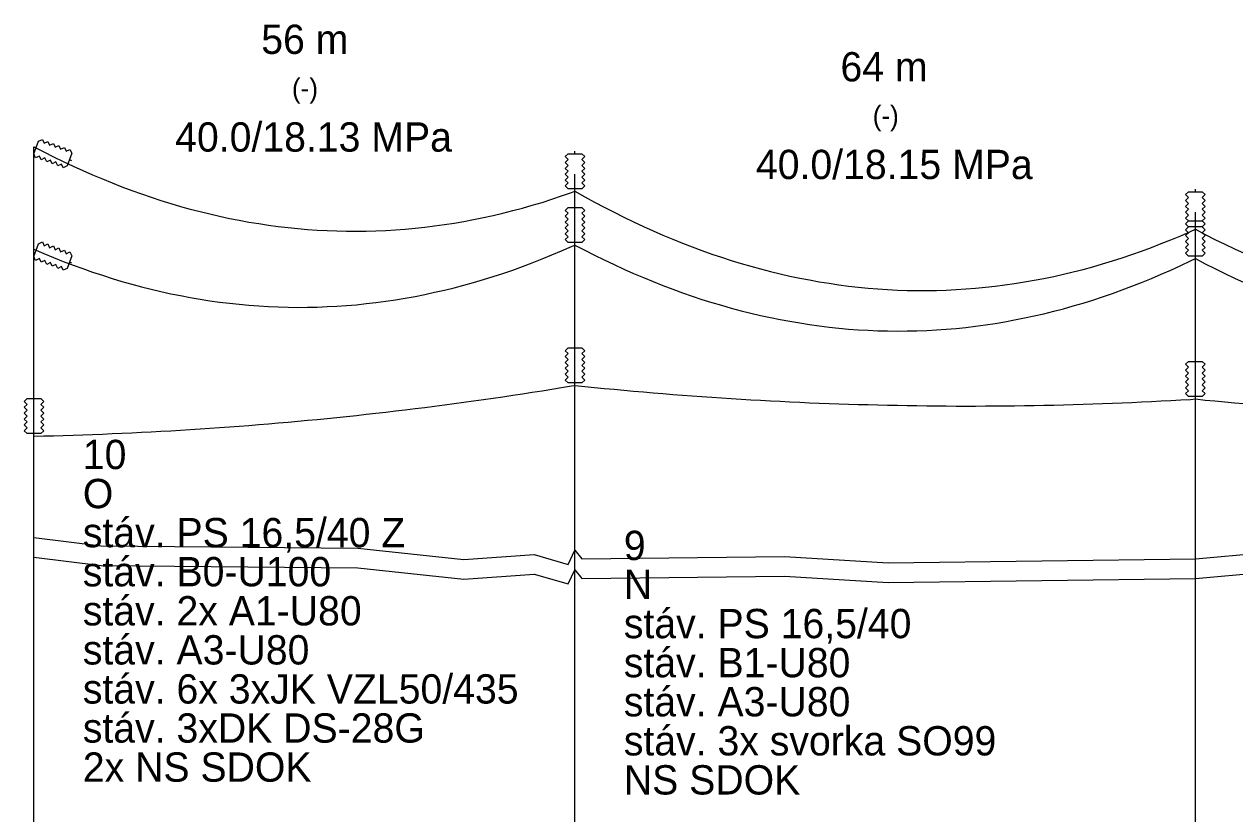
# Model space of a CAD drawing. Extents: x -21 to 628, y 809 to 990.
# Drawn here: x -1 to 122.9, y 900 to 980.8 of the extents above; entities that cross this region are included whole.
import ezdxf

# ---------------------------------------------------------------- set-up
doc = ezdxf.new("R2010")
doc.units = 0
for name, color, linetype in [('Vrstva 11', 7, 'Continuous'), ('Vrstva 12', 7, 'Continuous'), ('Vrstva 13', 7, 'Continuous'), ('Vrstva 14', 7, 'Continuous'), ('Vrstva 15', 7, 'Continuous'), ('Vrstva 29', 7, 'Continuous'), ('Vrstva 3', 7, 'Continuous')]:
    doc.layers.add(name, color=color, linetype=linetype)

msp = doc.modelspace()

# ---------------------------------------------------------------- linework, layer by layer
at = {"layer": 'Vrstva 11'}
for points in [[(0, 968.25), (1, 967.73), (2, 967.23), (3, 966.74), (4, 966.27), (5, 965.82), (6, 965.38), (7, 964.95), (8, 964.55), (9, 964.16), (10, 963.78), (11, 963.42), (12, 963.08), (13, 962.76), (14, 962.45), (15, 962.15), (16, 961.87), (17, 961.61), (18, 961.37), (19, 961.14), (20, 960.92), (21, 960.72), (22, 960.54), (23, 960.38), (24, 960.23), (25, 960.09), (26, 959.98), (27, 959.88), (28, 959.79), (29, 959.72), (30, 959.67), (31, 959.63), (32, 959.61), (33, 959.6), (34, 959.62), (35, 959.64), (36, 959.69), (37, 959.75), (38, 959.82), (39, 959.91), (40, 960.02), (41, 960.14), (42, 960.28), (43, 960.44), (44, 960.61), (45, 960.8), (46, 961), (47, 961.22), (48, 961.46), (49, 961.71), (50, 961.98), (51, 962.26), (52, 962.56), (53, 962.88), (54, 963.21), (55, 963.56), (55.37, 963.69)], [(55.37, 963.69), (56.37, 963.13), (57.37, 962.58), (58.37, 962.05), (59.37, 961.54), (60.37, 961.04), (61.37, 960.55), (62.37, 960.09), (63.37, 959.64), (64.37, 959.2), (65.37, 958.78), (66.37, 958.38), (67.37, 957.99), (68.37, 957.62), (69.37, 957.27), (70.37, 956.93), (71.37, 956.61), (72.37, 956.3), (73.37, 956.01), (74.37, 955.74), (75.37, 955.48), (76.37, 955.24), (77.37, 955.01), (78.37, 954.8), (79.37, 954.61), (80.37, 954.43), (81.37, 954.27), (82.37, 954.12), (83.37, 953.99), (84.37, 953.88), (85.37, 953.78), (86.37, 953.7), (87.37, 953.63), (88.37, 953.58), (89.37, 953.55), (90.37, 953.53), (91.37, 953.53), (92.37, 953.55), (93.37, 953.58), (94.37, 953.63), (95.37, 953.69), (96.37, 953.77), (97.37, 953.86), (98.37, 953.98), (99.37, 954.1), (100.37, 954.25), (101.37, 954.41), (102.37, 954.58), (103.37, 954.77), (104.37, 954.98), (105.37, 955.21), (106.37, 955.45), (107.37, 955.7), (108.37, 955.97), (109.37, 956.26), (110.37, 956.57), (111.37, 956.89), (112.37, 957.22), (113.37, 957.57), (114.37, 957.94), (115.37, 958.33), (116.37, 958.73), (117.37, 959.14), (118.37, 959.58), (118.87, 959.8)], [(118.87, 959.8), (119.87, 959.28), (120.87, 958.77), (121.87, 958.28), (122.87, 957.81), (123.87, 957.35)], [(0, 957.75), (1, 957.32), (2, 956.91), (3, 956.51), (4, 956.13), (5, 955.77), (6, 955.42), (7, 955.09), (8, 954.77), (9, 954.47), (10, 954.19), (11, 953.92), (12, 953.67), (13, 953.43), (14, 953.21), (15, 953.01), (16, 952.82), (17, 952.65), (18, 952.49), (19, 952.35), (20, 952.23), (21, 952.12), (22, 952.03), (23, 951.95), (24, 951.89), (25, 951.85), (26, 951.82), (27, 951.81), (28, 951.82), (29, 951.84), (30, 951.88), (31, 951.93), (32, 952), (33, 952.08), (34, 952.19), (35, 952.3), (36, 952.44), (37, 952.59), (38, 952.75), (39, 952.93), (40, 953.13), (41, 953.35), (42, 953.58), (43, 953.82), (44, 954.08), (45, 954.36), (46, 954.66), (47, 954.97), (48, 955.29), (49, 955.63), (50, 955.99), (51, 956.37), (52, 956.76), (53, 957.17), (54, 957.59), (55, 958.03), (55.37, 958.19)], [(0, 957.75), (1, 957.32), (2, 956.91), (3, 956.51), (4, 956.13), (5, 955.77), (6, 955.42), (7, 955.09), (8, 954.77), (9, 954.47), (10, 954.19), (11, 953.92), (12, 953.67), (13, 953.43), (14, 953.21), (15, 953.01), (16, 952.82), (17, 952.65), (18, 952.49), (19, 952.35), (20, 952.23), (21, 952.12), (22, 952.03), (23, 951.95), (24, 951.89), (25, 951.85), (26, 951.82), (27, 951.81), (28, 951.82), (29, 951.84), (30, 951.88), (31, 951.93), (32, 952), (33, 952.08), (34, 952.19), (35, 952.3), (36, 952.44), (37, 952.59), (38, 952.75), (39, 952.93), (40, 953.13), (41, 953.35), (42, 953.58), (43, 953.82), (44, 954.08), (45, 954.36), (46, 954.66), (47, 954.97), (48, 955.29), (49, 955.63), (50, 955.99), (51, 956.37), (52, 956.76), (53, 957.17), (54, 957.59), (55, 958.03), (55.37, 958.19)], [(55.37, 958.19), (56.37, 957.67), (57.37, 957.16), (58.37, 956.67), (59.37, 956.19), (60.37, 955.73), (61.37, 955.29), (62.37, 954.86), (63.37, 954.45), (64.37, 954.05), (65.37, 953.68), (66.37, 953.31), (67.37, 952.97), (68.37, 952.63), (69.37, 952.32), (70.37, 952.02), (71.37, 951.74), (72.37, 951.47), (73.37, 951.22), (74.37, 950.98), (75.37, 950.77), (76.37, 950.56), (77.37, 950.38), (78.37, 950.21), (79.37, 950.05), (80.37, 949.91), (81.37, 949.79), (82.37, 949.68), (83.37, 949.59), (84.37, 949.52), (85.37, 949.46), (86.37, 949.42), (87.37, 949.39), (88.37, 949.38), (89.37, 949.39), (90.37, 949.41), (91.37, 949.45), (92.37, 949.51), (93.37, 949.58), (94.37, 949.66), (95.37, 949.76), (96.37, 949.88), (97.37, 950.02), (98.37, 950.17), (99.37, 950.34), (100.37, 950.52), (101.37, 950.72), (102.37, 950.93), (103.37, 951.16), (104.37, 951.41), (105.37, 951.67), (106.37, 951.95), (107.37, 952.25), (108.37, 952.56), (109.37, 952.89), (110.37, 953.23), (111.37, 953.59), (112.37, 953.97), (113.37, 954.36), (114.37, 954.77), (115.37, 955.19), (116.37, 955.63), (117.37, 956.09), (118.37, 956.56), (118.87, 956.8)], [(55.37, 958.19), (56.37, 957.67), (57.37, 957.16), (58.37, 956.67), (59.37, 956.19), (60.37, 955.73), (61.37, 955.29), (62.37, 954.86), (63.37, 954.45), (64.37, 954.05), (65.37, 953.68), (66.37, 953.31), (67.37, 952.97), (68.37, 952.63), (69.37, 952.32), (70.37, 952.02), (71.37, 951.74), (72.37, 951.47), (73.37, 951.22), (74.37, 950.98), (75.37, 950.77), (76.37, 950.56), (77.37, 950.38), (78.37, 950.21), (79.37, 950.05), (80.37, 949.91), (81.37, 949.79), (82.37, 949.68), (83.37, 949.59), (84.37, 949.52), (85.37, 949.46), (86.37, 949.42), (87.37, 949.39), (88.37, 949.38), (89.37, 949.39), (90.37, 949.41), (91.37, 949.45), (92.37, 949.51), (93.37, 949.58), (94.37, 949.66), (95.37, 949.76), (96.37, 949.88), (97.37, 950.02), (98.37, 950.17), (99.37, 950.34), (100.37, 950.52), (101.37, 950.72), (102.37, 950.93), (103.37, 951.16), (104.37, 951.41), (105.37, 951.67), (106.37, 951.95), (107.37, 952.25), (108.37, 952.56), (109.37, 952.89), (110.37, 953.23), (111.37, 953.59), (112.37, 953.97), (113.37, 954.36), (114.37, 954.77), (115.37, 955.19), (116.37, 955.63), (117.37, 956.09), (118.37, 956.56), (118.87, 956.8)], [(118.87, 956.8), (119.87, 956.28), (120.87, 955.77), (121.87, 955.28), (122.87, 954.81), (123.87, 954.35)], [(118.87, 956.8), (119.87, 956.28), (120.87, 955.77), (121.87, 955.28), (122.87, 954.81), (123.87, 954.35)], [(0, 938.62), (1, 938.65), (2, 938.67), (3, 938.7), (4, 938.73), (5, 938.76), (6, 938.8), (7, 938.84), (8, 938.88), (9, 938.92), (10, 938.97), (11, 939.02), (12, 939.07), (13, 939.12), (14, 939.18), (15, 939.24), (16, 939.3), (17, 939.37), (18, 939.43), (19, 939.5), (20, 939.58), (21, 939.65), (22, 939.73), (23, 939.81), (24, 939.89), (25, 939.98), (26, 940.06), (27, 940.16), (28, 940.25), (29, 940.34), (30, 940.44), (31, 940.54), (32, 940.65), (33, 940.75), (34, 940.86), (35, 940.97), (36, 941.09), (37, 941.21), (38, 941.33), (39, 941.45), (40, 941.57), (41, 941.7), (42, 941.83), (43, 941.96), (44, 942.1), (45, 942.23), (46, 942.38), (47, 942.52), (48, 942.66), (49, 942.81), (50, 942.96), (51, 943.12), (52, 943.27), (53, 943.43), (54, 943.59), (55, 943.76), (55.37, 943.82)], [(55.37, 943.82), (56.37, 943.71), (57.37, 943.61), (58.37, 943.51), (59.37, 943.42), (60.37, 943.33), (61.37, 943.23), (62.37, 943.15), (63.37, 943.06), (64.37, 942.98), (65.37, 942.9), (66.37, 942.82), (67.37, 942.75), (68.37, 942.67), (69.37, 942.6), (70.37, 942.54), (71.37, 942.47), (72.37, 942.41), (73.37, 942.35), (74.37, 942.3), (75.37, 942.24), (76.37, 942.19), (77.37, 942.14), (78.37, 942.1), (79.37, 942.05), (80.37, 942.01), (81.37, 941.97), (82.37, 941.94), (83.37, 941.9), (84.37, 941.87), (85.37, 941.85), (86.37, 941.82), (87.37, 941.8), (88.37, 941.78), (89.37, 941.76), (90.37, 941.75), (91.37, 941.73), (92.37, 941.73), (93.37, 941.72), (94.37, 941.71), (95.37, 941.71), (96.37, 941.71), (97.37, 941.72), (98.37, 941.72), (99.37, 941.73), (100.37, 941.74), (101.37, 941.76), (102.37, 941.77), (103.37, 941.79), (104.37, 941.81), (105.37, 941.84), (106.37, 941.87), (107.37, 941.9), (108.37, 941.93), (109.37, 941.96), (110.37, 942), (111.37, 942.04), (112.37, 942.08), (113.37, 942.13), (114.37, 942.18), (115.37, 942.23), (116.37, 942.28), (117.37, 942.34), (118.37, 942.39), (118.87, 942.43)], [(118.87, 942.43), (119.87, 942.32), (120.87, 942.23), (121.87, 942.13), (122.87, 942.04), (123.87, 941.95)]]:
    msp.add_lwpolyline(points, dxfattribs=at)
at = {"layer": 'Vrstva 14'}
for p, q in [((0, 898.25), (0, 968.25)), ((55.37, 896.94), (55.37, 965.44)), ((118.87, 896.05), (118.87, 961.55))]:
    msp.add_line(p, q, dxfattribs=at)
at = {"layer": 'Vrstva 29'}
for points in [[(0, 967.51), (0.47, 968.82), (0.86, 969), (1.04, 968.62), (1.42, 968.8), (1.6, 968.41), (1.99, 968.59), (2.17, 968.21), (2.55, 968.39), (2.73, 968), (3.11, 968.18), (3.29, 967.8), (3.68, 967.98), (3.86, 967.59), (3.38, 966.28), (2.99, 966.1), (2.81, 966.48), (2.43, 966.3), (2.25, 966.69), (1.87, 966.51), (1.69, 966.89), (1.3, 966.71), (1.12, 967.1), (0.74, 966.92), (0.56, 967.3), (0.17, 967.12)], [(56.07, 963.94), (54.67, 963.94), (54.37, 964.24), (54.67, 964.54), (54.37, 964.84), (54.67, 965.14), (54.37, 965.44), (54.67, 965.74), (54.37, 966.04), (54.67, 966.34), (54.37, 966.64), (54.67, 966.94), (54.37, 967.24), (54.67, 967.54), (56.07, 967.54), (56.37, 967.24), (56.07, 966.94), (56.37, 966.64), (56.07, 966.34), (56.37, 966.04), (56.07, 965.74), (56.37, 965.44), (56.07, 965.14), (56.37, 964.84), (56.07, 964.54), (56.37, 964.24)], [(56.07, 963.94), (54.67, 963.94), (54.37, 964.24), (54.67, 964.54), (54.37, 964.84), (54.67, 965.14), (54.37, 965.44), (54.67, 965.74), (54.37, 966.04), (54.67, 966.34), (54.37, 966.64), (54.67, 966.94), (54.37, 967.24), (54.67, 967.54), (56.07, 967.54), (56.37, 967.24), (56.07, 966.94), (56.37, 966.64), (56.07, 966.34), (56.37, 966.04), (56.07, 965.74), (56.37, 965.44), (56.07, 965.14), (56.37, 964.84), (56.07, 964.54), (56.37, 964.24)], [(119.57, 960.05), (118.17, 960.05), (117.87, 960.35), (118.17, 960.65), (117.87, 960.95), (118.17, 961.25), (117.87, 961.55), (118.17, 961.85), (117.87, 962.15), (118.17, 962.45), (117.87, 962.75), (118.17, 963.05), (117.87, 963.35), (118.17, 963.65), (119.57, 963.65), (119.87, 963.35), (119.57, 963.05), (119.87, 962.75), (119.57, 962.45), (119.87, 962.15), (119.57, 961.85), (119.87, 961.55), (119.57, 961.25), (119.87, 960.95), (119.57, 960.65), (119.87, 960.35)], [(56.07, 958.44), (54.67, 958.44), (54.37, 958.74), (54.67, 959.04), (54.37, 959.34), (54.67, 959.64), (54.37, 959.94), (54.67, 960.24), (54.37, 960.54), (54.67, 960.84), (54.37, 961.14), (54.67, 961.44), (54.37, 961.74), (54.67, 962.04), (56.07, 962.04), (56.37, 961.74), (56.07, 961.44), (56.37, 961.14), (56.07, 960.84), (56.37, 960.54), (56.07, 960.24), (56.37, 959.94), (56.07, 959.64), (56.37, 959.34), (56.07, 959.04), (56.37, 958.74)], [(56.07, 958.44), (54.67, 958.44), (54.37, 958.74), (54.67, 959.04), (54.37, 959.34), (54.67, 959.64), (54.37, 959.94), (54.67, 960.24), (54.37, 960.54), (54.67, 960.84), (54.37, 961.14), (54.67, 961.44), (54.37, 961.74), (54.67, 962.04), (56.07, 962.04), (56.37, 961.74), (56.07, 961.44), (56.37, 961.14), (56.07, 960.84), (56.37, 960.54), (56.07, 960.24), (56.37, 959.94), (56.07, 959.64), (56.37, 959.34), (56.07, 959.04), (56.37, 958.74)], [(56.07, 958.44), (54.67, 958.44), (54.37, 958.74), (54.67, 959.04), (54.37, 959.34), (54.67, 959.64), (54.37, 959.94), (54.67, 960.24), (54.37, 960.54), (54.67, 960.84), (54.37, 961.14), (54.67, 961.44), (54.37, 961.74), (54.67, 962.04), (56.07, 962.04), (56.37, 961.74), (56.07, 961.44), (56.37, 961.14), (56.07, 960.84), (56.37, 960.54), (56.07, 960.24), (56.37, 959.94), (56.07, 959.64), (56.37, 959.34), (56.07, 959.04), (56.37, 958.74)], [(56.07, 958.44), (54.67, 958.44), (54.37, 958.74), (54.67, 959.04), (54.37, 959.34), (54.67, 959.64), (54.37, 959.94), (54.67, 960.24), (54.37, 960.54), (54.67, 960.84), (54.37, 961.14), (54.67, 961.44), (54.37, 961.74), (54.67, 962.04), (56.07, 962.04), (56.37, 961.74), (56.07, 961.44), (56.37, 961.14), (56.07, 960.84), (56.37, 960.54), (56.07, 960.24), (56.37, 959.94), (56.07, 959.64), (56.37, 959.34), (56.07, 959.04), (56.37, 958.74)], [(119.57, 957.05), (118.17, 957.05), (117.87, 957.35), (118.17, 957.65), (117.87, 957.95), (118.17, 958.25), (117.87, 958.55), (118.17, 958.85), (117.87, 959.15), (118.17, 959.45), (117.87, 959.75), (118.17, 960.05), (117.87, 960.35), (118.17, 960.65), (119.57, 960.65), (119.87, 960.35), (119.57, 960.05), (119.87, 959.75), (119.57, 959.45), (119.87, 959.15), (119.57, 958.85), (119.87, 958.55), (119.57, 958.25), (119.87, 957.95), (119.57, 957.65), (119.87, 957.35)], [(119.57, 957.05), (118.17, 957.05), (117.87, 957.35), (118.17, 957.65), (117.87, 957.95), (118.17, 958.25), (117.87, 958.55), (118.17, 958.85), (117.87, 959.15), (118.17, 959.45), (117.87, 959.75), (118.17, 960.05), (117.87, 960.35), (118.17, 960.65), (119.57, 960.65), (119.87, 960.35), (119.57, 960.05), (119.87, 959.75), (119.57, 959.45), (119.87, 959.15), (119.57, 958.85), (119.87, 958.55), (119.57, 958.25), (119.87, 957.95), (119.57, 957.65), (119.87, 957.35)], [(0, 957.01), (0.47, 958.32), (0.86, 958.5), (1.04, 958.12), (1.42, 958.3), (1.6, 957.91), (1.99, 958.09), (2.17, 957.71), (2.55, 957.89), (2.73, 957.5), (3.11, 957.68), (3.29, 957.3), (3.68, 957.48), (3.86, 957.09), (3.38, 955.78), (2.99, 955.6), (2.81, 955.98), (2.43, 955.8), (2.25, 956.19), (1.87, 956.01), (1.69, 956.39), (1.3, 956.21), (1.12, 956.6), (0.74, 956.42), (0.56, 956.8), (0.17, 956.62)], [(0, 957.01), (0.47, 958.32), (0.86, 958.5), (1.04, 958.12), (1.42, 958.3), (1.6, 957.91), (1.99, 958.09), (2.17, 957.71), (2.55, 957.89), (2.73, 957.5), (3.11, 957.68), (3.29, 957.3), (3.68, 957.48), (3.86, 957.09), (3.38, 955.78), (2.99, 955.6), (2.81, 955.98), (2.43, 955.8), (2.25, 956.19), (1.87, 956.01), (1.69, 956.39), (1.3, 956.21), (1.12, 956.6), (0.74, 956.42), (0.56, 956.8), (0.17, 956.62)], [(56.07, 944.07), (54.67, 944.07), (54.37, 944.37), (54.67, 944.67), (54.37, 944.97), (54.67, 945.27), (54.37, 945.57), (54.67, 945.87), (54.37, 946.17), (54.67, 946.47), (54.37, 946.77), (54.67, 947.07), (54.37, 947.37), (54.67, 947.67), (56.07, 947.67), (56.37, 947.37), (56.07, 947.07), (56.37, 946.77), (56.07, 946.47), (56.37, 946.17), (56.07, 945.87), (56.37, 945.57), (56.07, 945.27), (56.37, 944.97), (56.07, 944.67), (56.37, 944.37)], [(119.57, 942.68), (118.17, 942.68), (117.87, 942.98), (118.17, 943.27), (117.87, 943.58), (118.17, 943.88), (117.87, 944.18), (118.17, 944.48), (117.87, 944.77), (118.17, 945.08), (117.87, 945.38), (118.17, 945.68), (117.87, 945.98), (118.17, 946.27), (119.57, 946.27), (119.87, 945.98), (119.57, 945.68), (119.87, 945.38), (119.57, 945.08), (119.87, 944.77), (119.57, 944.48), (119.87, 944.18), (119.57, 943.88), (119.87, 943.58), (119.57, 943.27), (119.87, 942.98)], [(0.7, 938.88), (-0.7, 938.88), (-1, 939.18), (-0.7, 939.48), (-1, 939.77), (-0.7, 940.08), (-1, 940.38), (-0.7, 940.68), (-1, 940.98), (-0.7, 941.27), (-1, 941.58), (-0.7, 941.88), (-1, 942.18), (-0.7, 942.48), (0.7, 942.48), (1, 942.18), (0.7, 941.88), (1, 941.58), (0.7, 941.27), (1, 940.98), (0.7, 940.68), (1, 940.38), (0.7, 940.08), (1, 939.77), (0.7, 939.48), (1, 939.18)]]:
    msp.add_lwpolyline(points, close=True, dxfattribs=at)
for points in [[(0, 968.25), (0.23, 968.16)], [(55.37, 967.54), (55.37, 967.79)], [(55.37, 967.54), (55.37, 967.79)], [(3.62, 966.93), (3.85, 966.85)], [(55.37, 963.69), (55.37, 963.94)], [(55.37, 963.69), (55.37, 963.94)], [(118.87, 963.65), (118.87, 963.9)], [(55.37, 962.04), (55.37, 962.29)], [(55.37, 962.04), (55.37, 962.29)], [(55.37, 962.04), (55.37, 962.29)], [(55.37, 962.04), (55.37, 962.29)], [(118.87, 960.65), (118.87, 960.9)], [(118.87, 960.65), (118.87, 960.9)], [(118.87, 959.8), (118.87, 960.05)], [(55.37, 958.19), (55.37, 958.44)], [(55.37, 958.19), (55.37, 958.44)], [(55.37, 958.19), (55.37, 958.44)], [(55.37, 958.19), (55.37, 958.44)], [(0, 957.75), (0.23, 957.66)], [(0, 957.75), (0.23, 957.66)], [(118.87, 956.8), (118.87, 957.05)], [(118.87, 956.8), (118.87, 957.05)], [(3.62, 956.43), (3.85, 956.35)], [(3.62, 956.43), (3.85, 956.35)], [(55.37, 947.67), (55.37, 947.92)], [(118.87, 946.27), (118.87, 946.52)], [(55.37, 943.82), (55.37, 944.07)], [(0, 942.48), (0, 942.73)], [(118.87, 942.43), (118.87, 942.68)], [(0, 938.62), (0, 938.88)]]:
    msp.add_lwpolyline(points, dxfattribs=at)
at = {"layer": 'Vrstva 3'}
for p, q in [((0, 928.25), (6.86, 927.4)), ((6.86, 927.4), (33.13, 927.15)), ((33.13, 927.15), (43.99, 926)), ((54.66, 925.5), (55.36, 926.95)), ((55.36, 926.95), (55.37, 926.94)), ((55.37, 926.94), (56.06, 926.05)), ((118.87, 926.05), (136.97, 927.7)), ((0, 926.25), (6.86, 925.4)), ((0, 926.25), (6.86, 925.4)), ((0, 926.25), (6.86, 925.4)), ((43.99, 926), (51.19, 926.5)), ((51.19, 926.5), (54.66, 925.5)), ((56.06, 926.05), (76.8, 926.3)), ((76.8, 926.3), (87.41, 925.65)), ((87.41, 925.65), (118.87, 926.05)), ((118.87, 924.05), (136.97, 925.7)), ((118.87, 924.05), (136.97, 925.7)), ((118.87, 924.05), (136.97, 925.7)), ((6.86, 925.4), (33.13, 925.15)), ((6.86, 925.4), (33.13, 925.15)), ((6.86, 925.4), (33.13, 925.15)), ((33.13, 925.15), (43.99, 924)), ((33.13, 925.15), (43.99, 924)), ((33.13, 925.15), (43.99, 924)), ((43.99, 924), (51.19, 924.5)), ((43.99, 924), (51.19, 924.5)), ((43.99, 924), (51.19, 924.5)), ((51.19, 924.5), (54.66, 923.5)), ((51.19, 924.5), (54.66, 923.5)), ((51.19, 924.5), (54.66, 923.5)), ((54.66, 923.5), (55.36, 924.95)), ((54.66, 923.5), (55.36, 924.95)), ((54.66, 923.5), (55.36, 924.95)), ((55.36, 924.95), (55.37, 924.94)), ((55.36, 924.95), (55.37, 924.94)), ((55.36, 924.95), (55.37, 924.94)), ((55.37, 924.94), (56.06, 924.05)), ((55.37, 924.94), (56.06, 924.05)), ((55.37, 924.94), (56.06, 924.05)), ((56.06, 924.05), (76.8, 924.3)), ((56.06, 924.05), (76.8, 924.3)), ((56.06, 924.05), (76.8, 924.3)), ((76.8, 924.3), (87.41, 923.65)), ((76.8, 924.3), (87.41, 923.65)), ((76.8, 924.3), (87.41, 923.65)), ((87.41, 923.65), (118.87, 924.05)), ((87.41, 923.65), (118.87, 924.05)), ((87.41, 923.65), (118.87, 924.05))]:
    msp.add_line(p, q, dxfattribs=at)

# ---------------------------------------------------------------- texts
at = {"layer": 'Vrstva 12'}
for s, p in [('40.0/18.13 MPa', (14.45, 967.75)), ('40.0/18.15 MPa', (73.89, 964.94))]:
    msp.add_text(s, height=3, dxfattribs=at).set_placement(p)
at = {"layer": 'Vrstva 13'}
for s, height, p in [('56 m', 3, (23.26, 977.75)), ('64 m', 3, (82.54, 974.94)), ('(-)', 2, (26.4, 973.25)), ('(-)', 2, (85.84, 970.44))]:
    msp.add_text(s, height=height, dxfattribs=at).set_placement(p)
at = {"layer": 'Vrstva 15'}
for s, p in [('10', (5, 935.25)), ('O', (5, 931.25)), ('stáv. PS 16,5/40 Z', (5, 927.25)), ('9', (60.37, 925.94)), ('stáv. B0-U100', (5, 923.25)), ('N', (60.37, 921.94)), ('stáv. 2x A1-U80', (5, 919.25)), ('stáv. PS 16,5/40', (60.37, 917.94)), ('stáv. A3-U80', (5, 915.25)), ('stáv. B1-U80', (60.37, 913.94)), ('stáv. 6x 3xJK VZL50/435', (5, 911.25)), ('stáv. A3-U80', (60.37, 909.94)), ('stáv. 3xDK DS-28G', (5, 907.25)), ('stáv. 3x svorka SO99', (60.37, 905.94)), ('2x NS SDOK', (5, 903.25)), ('NS SDOK', (60.37, 901.94))]:
    msp.add_text(s, height=3, dxfattribs=at).set_placement(p)

doc.saveas('drawing.dxf')
